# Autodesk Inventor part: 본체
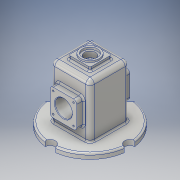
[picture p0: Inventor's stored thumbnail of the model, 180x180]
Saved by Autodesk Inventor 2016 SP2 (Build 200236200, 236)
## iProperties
Created: 2018-07
Part Number: 본체
Material: 알루미늄 6061
Document SubType Name: Modeling
Designer: Administrator
Density: 2.7 g/cm^3
Appearance: 알루미늄 - 평지
Mass: 905.953 g
Surface Area: 1026.21 cm^2
Volume: 335.538 cm^3
Author: Administrator
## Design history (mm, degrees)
sketch "스케치11"
  geometry: L1 (-37, -37)-(37, -37); L2 (37, -37)-(37, 37); L3 (37, 37)-(-37, 37); L4 (-37, 37)-(-37, -37); L5 (-37, -37)-(37, 37); L6 (37, -37)-(-37, 37); 1 further point
  constraints: 12 end point, 2 midpoint, 2 parallel, 1 horizontal, 1 perpendicular
  dimensions: "d36" = 74 distance of L3.end L2.end; "d37" = 74 distance of L2.end L1.end
extrude "돌출9" new body sketch "스케치11" distance "d38" = 100; taper "d39" = 0 deg
feature "쉘2" dims "d40" = 5
sketch "스케치12"
  geometry: L1 (20, -20)-(-20, -20); L2 (-20, -20)-(-20, 20); L3 (-20, 20)-(20, 20); L4 (20, 20)-(20, -20); L5 (20, -20)-(-20, 20); L6 (-20, -20)-(20, 20); 1 further point
  constraints: 12 end point, 2 midpoint, 2 parallel, 1 horizontal, 1 perpendicular
  dimensions: "d41" = 40 distance of L2.end L3.end; "d42" = 40 distance of L1.end L2.end
extrude "돌출10" join sketch "스케치12" distance "d43" = 7; taper "d44" = 0 deg
sketch "스케치14"
  geometry: A1 r 75 centre (0, 0) between (74.333, 9.978) and (9.978, 74.333); A2 r 10 centre (75, 0) between (74.333, -9.978) and (74.333, 9.978); A3 r 10 centre (0, -75) between (-9.978, -74.333) and (9.978, -74.333); A4 r 10 centre (-75, 0) between (-74.333, -9.978) and (-74.333, 9.978); A5 r 10 centre (0, 75) between (-9.978, 74.333) and (9.978, 74.333); A6 r 75 centre (0, 0) between (74.333, -9.978) and (74.333, 9.978); A7 r 75 centre (0, 0) between (-9.978, -74.333) and (9.978, -74.333); A8 r 75 centre (0, 0) between (9.978, -74.333) and (74.333, -9.978); A9 r 75 centre (0, 0) between (-74.333, -9.978) and (-9.978, -74.333); A10 r 75 centre (0, 0) between (-74.333, 9.978) and (-74.333, -9.978); A11 r 75 centre (0, 0) between (-9.978, 74.333) and (-74.333, 9.978); A12 r 75 centre (0, 0) between (9.978, 74.333) and (-9.978, 74.333); 1 further point
  constraints: 38 point on circle, 12 centre point, 2 horizontal alignment, 2 vertical alignment, 1 coincident
  dimensions: "d48" = 150 diameter of A1; "d49" = 20 diameter of A2; "d50" = 20 diameter of A3; "d51" = 20 diameter of A4; "d52" = 20 diameter of A5
extrude "돌출12" join sketch "스케치14" distance "d53" = 10; taper "d54" = 0 deg
sketch "스케치15"
  geometry: L1 (-37.333, -110)-(27.022, -110) reference; L2 (62, -30)-(12, -30); L3 (12, -30)-(12, -80); L4 (12, -80)-(62, -80); L5 (62, -80)-(62, -30); L6 (62, -30)-(12, -80); L7 (12, -30)-(62, -80); 2 further points
  constraints: 12 end point, 2 midpoint, 2 parallel, 1 horizontal, 1 perpendicular, 1 vertical alignment
  dimensions: "d55" = 50 distance of L4.end L3.end; "d56" = 50 distance of L3.end L2.end; "d57" = 55 distance from line of L1 point (37, -55)
extrude "돌출13" join sketch "스케치15" distance "d58" = 13; taper "d59" = 0 deg
sketch "스케치16"
  geometry: L1 (-37.333, -110)-(27.022, -110) reference; L2 (62, -30)-(12, -30); L3 (12, -30)-(12, -80); L4 (12, -80)-(62, -80); L5 (62, -80)-(62, -30); L6 (62, -30)-(12, -80); L7 (12, -30)-(62, -80); 3 further points
  constraints: 12 end point, 3 midpoint, 2 parallel, 1 horizontal, 1 perpendicular, 1 vertical alignment
  dimensions: "d60" = 50 distance of L4.end L3.end; "d61" = 50 distance of L3.end L2.end; "d62" = 55 distance from line of L1 point (37, -55)
extrude "돌출14" join sketch "스케치16" distance "d63" = 13; taper "d64" = 0 deg
sketch "스케치17"
  geometry: L1 (70, 37)-(70, 50) reference; L2 (5, 32)-(95, 32) reference; L3 (70, -37)-(70, -50) reference; L4 (5, -32)-(95, -32) reference; L5 (70, 50)-(20, 50) reference; L6 (20, -50)-(70, -50) reference; L7 (45, 32)-(45, -32); L8 (0, -9.978)-(0, -74.333) reference; L9 (0, -74.333)-(-10, -74.333) reference; L10 (-10, -9.978)-(-10, -74.333) reference; L11 (0, -9.978)-(-10, -9.978) reference; L12 (45, 32)-(70, 32); L13 (70, 32)-(67.452, 25); L14 (67.452, 25)-(45, 25); L15 (45, 32)-(45, 25); 1 further point
  constraints: 10 end point, 4 point on line, 2 perpendicular, 1 collinear, 1 vertical alignment
  dimensions: "d68" = 55 distance between parallel lines of L10 L7; "d69" = 7 vertical distance of L13.end L12.end; "d70" = 110 deg angle of L2 L13
revolve "회전1" sketch "스케치17" stored, may be unused: angle "d71" = 90 deg
sketch "스케치18"
  geometry: L1 (-37.333, -110)-(27.022, -110) reference; C1 r 16 at (37, -55); 1 further point
  constraints: 1 centre point, 1 vertical alignment
  dimensions: "d72" = 32 diameter of C1; "d73" = 55 distance from line of L1 C1.centre
extrude "돌출15" cut sketch "스케치18" stored distance "d74" = 13; taper "d75" = 0 deg
sketch "스케치19"
  geometry: L1 (32, 32)-(-32, 32); L2 (-32, 32)-(-32, -32); L3 (-32, -32)-(32, -32); L4 (32, -32)-(32, 32); L5 (32, 32)-(-32, -32); L6 (-32, 32)-(32, -32); 1 further point
  constraints: 12 end point, 2 midpoint, 2 parallel, 1 horizontal, 1 perpendicular
  dimensions: "d76" = 64 distance of L3.end L2.end; "d77" = 64 distance of L2.end L1.end
extrude "돌출16" cut sketch "스케치19" stored distance "d78" = 13; taper "d79" = 0 deg
fillet "모깎기1" dims "d83" = 6
sketch "스케치22"
  geometry: L1 (62, -36)-(62, -74) reference; L2 (56, -80)-(18, -80) reference; L3 (12, -74)-(12, -36) reference; L4 (18, -30)-(56, -30) reference; L5 (0, -100)-(74, -100) reference; L6 (74, -100)-(74, 0) reference; L7 (0, 0)-(74, 0) reference; L8 (0, -100)-(0, 0) reference; A1 r 6 centre (56, -74) between (56, -80) and (62, -74) reference; A2 r 6 centre (18, -74) between (12, -74) and (18, -80) reference; A3 r 6 centre (18, -36) between (18, -30) and (12, -36) reference; A4 r 6 centre (56, -36) between (62, -36) and (56, -30) reference; 5 further points
  constraints: 4 coincident
hole "구멍1" sketch "스케치22" at (18, -36), (56, -36), (56, -74), (18, -74) diameter "d84" = 3.242; stored, may be unused: countersink angle "d88" = 90 deg, drill point angle "d90" = 118 deg; dims "d85" = 8, "d86" = 4, "d87" = 2, "d89" = 10
fillet "모깎기2" dims "d91" = 8
chamfer "모따기1" distance "d92" = 1; stored, may be unused: second distance "d93" = 2, angle "d94" = 45 deg
fillet "모깎기3" dims "d95" = 3
fillet "모깎기4" dims "d96" = 3
fillet "모깎기5" dims "d97" = 3
fillet "모깎기6" dims "d98" = 3
sketch "스케치23"
  geometry: C1 r 17.5 at (0, 0); 1 further point
  constraints: 1 centre point, 1 coincident
  dimensions: "d99" = 35 diameter of C1
extrude "돌출18" join sketch "스케치23" distance "d100" = 3; taper "d101" = 0 deg
sketch "스케치24"
  geometry: C1 r 14 at (0, 0); 1 further point
  constraints: 1 centre point, 1 coincident
  dimensions: "d102" = 28 diameter of C1
extrude "돌출19" cut sketch "스케치24" distance "d103" = 4; taper "d104" = 0 deg
sketch "스케치25"
  geometry: C1 r 10.5 at (0, 0); 1 further point
  constraints: 1 centre point, 1 coincident
  dimensions: "d105" = 21 diameter of C1
extrude "돌출20" cut sketch "스케치25" stored distance "d106" = 4; taper "d107" = 0 deg
sketch "스케치26"
  geometry: L1 (66, -89)-(66, 0) reference; L2 (46.5, 18)-(11.5, 18) reference; 2 further points
  constraints: 1 other
  dimensions: "d108" = 30 distance from line of L2 point (29, -12); "d109" = 37 distance from line of L1 point (29, -12)
feature "엠보싱1" sketch "스케치26" dims "d36" = 74, "d37" = 74, "d110" = 0.5, "d111" = 0
fillet "모깎기7" dims "d112" = 3
fillet "모깎기8" dims "d113" = 3
node "솔리드2"
mirror "대칭1"
mirror "대칭2"
node "투영된 루프6"
node "투영된 루프7"
